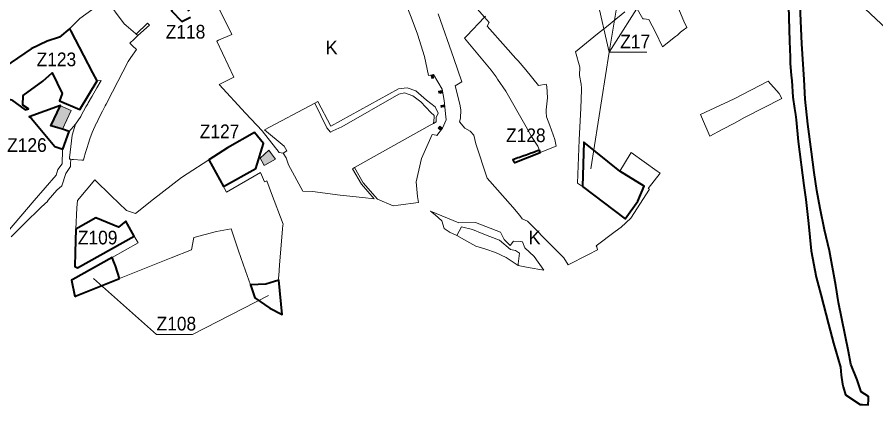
# Model space of a CAD drawing. Extents: x -650276 to -642489, y -1074425 to -1066658.
# Drawn here: x -646722 to -645214, y -1073293 to -1072612 of the extents above; entities that cross this region are included whole.
import ezdxf

# ---------------------------------------------------------------- set-up
doc = ezdxf.new("R2010")
doc.units = 0
doc.header["$LTSCALE"] = 9.6
for name, color, linetype, lineweight in [('1', 7, 'Continuous', 13), ('43', 7, 'Continuous', 13), ('44', 7, 'Continuous', 40), ('45', 7, 'Continuous', 40), ('46', 7, 'Continuous', 13), ('47', 7, 'Continuous', 13)]:
    doc.layers.add(name, color=color, linetype=linetype, lineweight=lineweight)

msp = doc.modelspace()

# ---------------------------------------------------------------- hatches: boundary and pattern name
at = {"layer": '1'}
for points in [[(-645995.13, -1072714.74), (-645994.08, -1072719.72), (-645990.99, -1072719.21), (-645991.83, -1072714.17)], [(-645982.09, -1072742.2), (-645981.54, -1072745.4), (-645979.54, -1072744.94), (-645979.29, -1072745.98), (-645975.96, -1072745.2), (-645976.91, -1072741.11)], [(-646663.07, -1072803.04), (-646653.02, -1072806.07), (-646643.01, -1072809.08), (-646627.38, -1072776.23), (-646636.84, -1072771.74), (-646636.98, -1072772.03), (-646646.39, -1072767.9)], [(-645978.31, -1072767.48), (-645977.69, -1072770.55), (-645976.22, -1072770.26), (-645972.21, -1072769.44), (-645972.83, -1072766.36), (-645976.84, -1072767.17)], [(-645980.16, -1072803.63), (-645976.62, -1072806.59), (-645978.86, -1072809.21), (-645979.48, -1072809.98), (-645982.99, -1072807.15), (-645982.37, -1072806.37)], [(-646295.37, -1072859.86), (-646289.57, -1072870.47), (-646288.95, -1072871.78), (-646287.48, -1072872.3), (-646268.48, -1072861.81), (-646277.43, -1072849.63), (-646280.32, -1072845.93)]]:
    msp.add_hatch(color=256, dxfattribs=at).paths.add_polyline_path(points)

# ---------------------------------------------------------------- linework, layer by layer
for points in [[(-645201.69, -1072577.19), (-645220.27, -1072560.51), (-645223.86, -1072557.28), (-645231.56, -1072550.37), (-645240, -1072542.79), (-645247.59, -1072535.97), (-645252.12, -1072535.29), (-645265.009, -1072538.358), (-645252.768, -1072552.178), (-645248.967, -1072559.511), (-645249.9, -1072561.25), (-645248.8, -1072562.32), (-645250.27, -1072563.1), (-645261.57, -1072569.842), (-645242, -1072588.6), (-645185.95, -1072641.32)], [(-645899.69, -1072610.7), (-645901.33, -1072612.4), (-645935.38, -1072573)], [(-646524.818, -1072657.852), (-646517.19, -1072650.7), (-646511.84, -1072645.84), (-646510.28, -1072644.42), (-646531.13, -1072626.73), (-646534.36, -1072624), (-646566.49, -1072579.96), (-646591.49, -1072599.19), (-646612.66, -1072614.57), (-646618.94, -1072620.88), (-646629.86, -1072632.07), (-646627.32, -1072636.95), (-646605.23, -1072679.37), (-646589.37, -1072709.83)], [(-645635.96, -1072593.24), (-645623.21, -1072614.93), (-645620.91, -1072615.18), (-645612.67, -1072616.12), (-645601.4, -1072638.87), (-645588.81, -1072664.3), (-645565.89, -1072646.15), (-645562.23, -1072643.9), (-645557.19, -1072638.59), (-645554.79, -1072636.89), (-645552.52, -1072635.29), (-645546.18, -1072630.68), (-645551.5, -1072619.44), (-645566.54, -1072582.88)], [(-645982.84, -1072606.46), (-645955.51, -1072684.762), (-645941.146, -1072725.78), (-645953.06, -1072733.07), (-645944.81, -1072765.04), (-645943.38, -1072774.7), (-645943.65, -1072789.47), (-645945.37, -1072795.9), (-645936.23, -1072806.92), (-645926.95, -1072812.63), (-645920.56, -1072819.2), (-645916.48, -1072834.69), (-645896.61, -1072895.14), (-645851.64, -1072945.67), (-645839.57, -1072960.36), (-645835.46, -1072966.49), (-645825.96, -1072970.48), (-645781.57, -1073015.6), (-645767.281, -1073029.7), (-645761.93, -1073034.98), (-645754.82, -1073046.89), (-645741.57, -1073040.34), (-645732.99, -1073036.05), (-645723.5, -1073031.08), (-645719.13, -1073028.84), (-645703.2, -1073020.63), (-645704.37, -1073015.6), (-645705.58, -1073013.4), (-645671.84, -1072988.43), (-645661.51, -1072981.17), (-645644.66, -1072964.8)], [(-645654.16, -1072966.3), (-645729.36, -1072909.65), (-645738.444, -1072903.485), (-645735.02, -1072827.73), (-645732.514, -1072771.845), (-645731.07, -1072739.66), (-645731.28, -1072737.01), (-645731.97, -1072730.04), (-645734.45, -1072714.58), (-645734.19, -1072700.16), (-645741.87, -1072673.02), (-645703.02, -1072641.66), (-645684.57, -1072626.76), (-645677.56, -1072621.1), (-645655.18, -1072603.04)], [(-645936.92, -1072649.21), (-645932.72, -1072644.86), (-645901.33, -1072612.4), (-645893.16, -1072621.85)], [(-645893.16, -1072621.85), (-645897.1, -1072627.93), (-645864.52, -1072664.38), (-645846.45, -1072684.59)], [(-645846.45, -1072684.59), (-645842.51, -1072689.16), (-645828.86, -1072704.98), (-645806.42, -1072732.23), (-645793.25, -1072730.08), (-645792.17, -1072734.14), (-645790.73, -1072753.95), (-645792.92, -1072775.02), (-645793.04, -1072779.12), (-645792.36, -1072786.94), (-645786.89, -1072802.48), (-645778.21, -1072827.14), (-645775.56, -1072838.69), (-645803.84, -1072849.72), (-645805.66, -1072844.58), (-645807.79, -1072838.57), (-645818.73, -1072821.79), (-645828.3, -1072804.78), (-645863.93, -1072742.28), (-645878.65, -1072720.99), (-645881.28, -1072717.18), (-645889.59, -1072705.17), (-645936.92, -1072649.21)], [(-646513.05, -1072668.97), (-646519.93, -1072662.47), (-646524.818, -1072657.852)], [(-646589.37, -1072709.83), (-646581.92, -1072723.91), (-646575.17, -1072723.31), (-646582.42, -1072736.04), (-646590.83, -1072750.81), (-646591.82, -1072752.54), (-646597.52, -1072762.54), (-646598.51, -1072764.27), (-646601.72, -1072769.92), (-646605.93, -1072777.31), (-646610.53, -1072786.11), (-646610.86, -1072786.74), (-646620.27, -1072799.95), (-646625.91, -1072819.66), (-646630.45, -1072858.93), (-646630.57, -1072859.99), (-646630.76, -1072861.61), (-646628.36, -1072861.71), (-646625.96, -1072861.88), (-646625.3, -1072861.92), (-646623.67, -1072862.03), (-646623.25, -1072862.05), (-646608.7, -1072863.05), (-646606.09, -1072863.23), (-646605.32, -1072860.63), (-646602.37, -1072849.93), (-646600.35, -1072843.05), (-646597.38, -1072833.61), (-646594.89, -1072825.68), (-646590.47, -1072814.45), (-646582.98, -1072797.91), (-646582.77, -1072797.45), (-646579.08, -1072789.5), (-646572.45, -1072777.28), (-646567.66, -1072768.09), (-646566, -1072764.9), (-646558.8, -1072750.3), (-646557.83, -1072748.33), (-646555.29, -1072743.47), (-646527.32, -1072689.94), (-646522.77, -1072683), (-646513.05, -1072668.97)], [(-646354.771, -1072919.554), (-646385.86, -1072862.59), (-646423.91, -1072887.04), (-646433.87, -1072893.44), (-646483, -1072931.63), (-646514.85, -1072956.93)], [(-645644.66, -1072964.8), (-645611.65, -1072913.96), (-645613.92, -1072912.93), (-645592.88, -1072886.26), (-645594.56, -1072885.17), (-645598.47, -1072882.66), (-645643.99, -1072849.85), (-645645.63, -1072852.72), (-645663.52, -1072882.58), (-645620.92, -1072908.65), (-645632.23, -1072935.28), (-645654.16, -1072966.3)], [(-646514.85, -1072956.93), (-646530.4, -1072951.72), (-646557.34, -1072925.73), (-646586.22, -1072897.88), (-646616.49, -1072934), (-646617.93, -1072946.87), (-646619.48, -1072984.34), (-646584.23, -1072964.22), (-646544.68, -1072980.62), (-646531.46, -1072970.12), (-646516.7, -1072996.65), (-646514.97, -1072999.69), (-646510.117, -1073008.522), (-646555.79, -1073033.92), (-646550.01, -1073048.55), (-646542.62, -1073071.1), (-646452.08, -1073034.96), (-646415.94, -1073020.53), (-646412.31, -1072999.06), (-646372.47, -1072988.24), (-646346.69, -1072983.91), (-646333.54, -1073022.2), (-646321.46, -1073057.38), (-646312.87, -1073082.4), (-646285.77, -1073081.01), (-646262.94, -1073074.15), (-646263.36, -1073069.88), (-646263.01, -1073065.63), (-646261.54, -1073047.75), (-646256.25, -1072983.65), (-646255.79, -1072978.09), (-646255.41, -1072975.67), (-646275.58, -1072921.83), (-646283.96, -1072899.46), (-646288.06, -1072901.13), (-646294.78, -1072885.04), (-646354.771, -1072919.554)]]:
    msp.add_lwpolyline(points, dxfattribs=at)
for points in [[(-645995.13, -1072714.74), (-645994.08, -1072719.72), (-645990.99, -1072719.21), (-645991.83, -1072714.17)], [(-645505.43, -1072820.89), (-645483.94, -1072809.44), (-645462.66, -1072798.09), (-645444.62, -1072788.65), (-645379.03, -1072755.22), (-645384.11, -1072746.12), (-645403, -1072724.61), (-645463.12, -1072755.6), (-645522.24, -1072783.2)], [(-645982.09, -1072742.2), (-645981.54, -1072745.4), (-645979.54, -1072744.94), (-645979.29, -1072745.98), (-645975.96, -1072745.2), (-645976.91, -1072741.11)], [(-646199.72, -1072763.1), (-646178.75, -1072806.5), (-646171.77, -1072814.14), (-646168.17, -1072812.07), (-646152.26, -1072804.66), (-646052.23, -1072747.56), (-646041.81, -1072745.33), (-646027.3, -1072750.14), (-646013.15, -1072760.96), (-645995.95, -1072779.42), (-645989.88, -1072784.99), (-645990.23, -1072788.27), (-645991.37, -1072798.84), (-645996.8, -1072801.88), (-646129.91, -1072876.24), (-646133.31, -1072878.61), (-646117.66, -1072905.49), (-646095.6, -1072931.21), (-646115.72, -1072928.91), (-646154.82, -1072924.44), (-646203.72, -1072918.45), (-646220.64, -1072917.46), (-646245.69, -1072871.45), (-646250.05, -1072859.17), (-646255.39, -1072850.83), (-646249.04, -1072847.16), (-646253.56, -1072838.8), (-646288.27, -1072810.22)], [(-646663.07, -1072803.04), (-646653.02, -1072806.07), (-646643.01, -1072809.08), (-646627.38, -1072776.23), (-646636.84, -1072771.74), (-646636.98, -1072772.03), (-646646.39, -1072767.9)], [(-645978.31, -1072767.48), (-645977.69, -1072770.55), (-645976.22, -1072770.26), (-645972.21, -1072769.44), (-645972.83, -1072766.36), (-645976.84, -1072767.17)], [(-645980.16, -1072803.63), (-645976.62, -1072806.59), (-645978.86, -1072809.21), (-645979.48, -1072809.98), (-645982.99, -1072807.15), (-645982.37, -1072806.37)], [(-646295.37, -1072859.86), (-646289.57, -1072870.47), (-646288.95, -1072871.78), (-646287.48, -1072872.3), (-646268.48, -1072861.81), (-646277.43, -1072849.63), (-646280.32, -1072845.93)], [(-645949.85, -1072995.57), (-645932.44, -1073005.5), (-645916.47, -1073014.03), (-645899.35, -1073019.65), (-645882.07, -1073025.22), (-645863.39, -1073034.25), (-645842.53, -1073048.19), (-645842.16, -1073045.21), (-645839.85, -1073026.66), (-645847.19, -1073022.14), (-645855.78, -1073020.17), (-645875.33, -1073003.99), (-645892.03, -1072997.34), (-645905.7, -1072991.86), (-645922.38, -1072985.16), (-645941.84, -1072980.05)]]:
    msp.add_lwpolyline(points, close=True, dxfattribs=at)
at = {"layer": '44'}
for points in [[(-645369.364, -1072485.931), (-645372.72, -1072490.314), (-645370.928, -1072496.619), (-645370.755, -1072525.734), (-645368.173, -1072571.881), (-645366.022, -1072654.462), (-645364.524, -1072682.575), (-645364.786, -1072692.977), (-645362.708, -1072714.781)], [(-645338.023, -1072755.969), (-645339.96, -1072721.587), (-645344.152, -1072658.857), (-645347.795, -1072577.893), (-645347.214, -1072540.97), (-645348.253, -1072505.583), (-645347.292, -1072502.877)], [(-645362.708, -1072714.781), (-645361.874, -1072723.527), (-645359.76, -1072752.865), (-645357.272, -1072772.771), (-645355.121, -1072782.993)], [(-645317.65, -1072916.642), (-645322.284, -1072885.085), (-645327.091, -1072848.387), (-645333.718, -1072799.987), (-645338.023, -1072755.969)], [(-645355.121, -1072782.993), (-645354.019, -1072792.454), (-645350.822, -1072830.388), (-645340.345, -1072908.029), (-645337.34, -1072932.073), (-645332.517, -1072974.538), (-645327.554, -1073022.214), (-645319.052, -1073068.6), (-645310.558, -1073098.946), (-645297.395, -1073151.294), (-645288.647, -1073184.518), (-645276.125, -1073226.571), (-645275.269, -1073240.71), (-645272.747, -1073256.762), (-645271.518, -1073261.16)], [(-645304.24, -1072985.372), (-645311.772, -1072947.945), (-645317.65, -1072916.642)], [(-645257.842, -1073221.36), (-645262.388, -1073199.409), (-645279.878, -1073113.356), (-645284.269, -1073083.286), (-645295.788, -1073022.556), (-645304.24, -1072985.372)], [(-645237.524, -1073292.361), (-645227.744, -1073292.735), (-645227.199, -1073283.366), (-645226.847, -1073278.345), (-645239.9, -1073270.025), (-645247.051, -1073248.736), (-645257.842, -1073221.36)], [(-645271.518, -1073261.16), (-645267.525, -1073275.443), (-645241.72, -1073292.2), (-645237.524, -1073292.361)]]:
    msp.add_lwpolyline(points, dxfattribs=at)
at = {"layer": '45'}
for points in [[(-646420.36, -1072601.78), (-646427.95, -1072588.07), (-646432.57, -1072579.75), (-646433.36, -1072578.45), (-646451.458, -1072601.008), (-646433.024, -1072620.04), (-646417.787, -1072612.168)], [(-646737.05, -1072756.4), (-646732.5, -1072757.63), (-646708.65, -1072775.02), (-646702.45, -1072773.39), (-646712.46, -1072766.76), (-646711.79, -1072750.02), (-646677.39, -1072724.85), (-646660.89, -1072709.97), (-646643.36, -1072746.04), (-646647.93, -1072759.01), (-646612.11, -1072774.56), (-646581.92, -1072723.91), (-646589.37, -1072709.83), (-646605.23, -1072679.37), (-646627.32, -1072636.95), (-646629.86, -1072632.07), (-646648.27, -1072647.48), (-646669.6, -1072654.53), (-646697.89, -1072667.65)], [(-646697.89, -1072667.65), (-646732.95, -1072691.68), (-646759.491, -1072709.878), (-646757.5, -1072713.3), (-646747.87, -1072729.85), (-646744.94, -1072734.88), (-646748.3, -1072737.01), (-646737.05, -1072756.4)], [(-646653.02, -1072806.07), (-646663.07, -1072803.04), (-646663.07, -1072803.04), (-646646.12, -1072767.32), (-646646.31, -1072767.388), (-646701.12, -1072787.08), (-646697.09, -1072790.03), (-646656.36, -1072839.08)], [(-646656.36, -1072839.08), (-646642.404, -1072844.195), (-646631.08, -1072812.68), (-646643.01, -1072809.08), (-646651.11, -1072806.64), (-646653.02, -1072806.07)], [(-645849.703, -1072867.622), (-645848.52, -1072867.16), (-645803.84, -1072849.72), (-645805.159, -1072845.994)], [(-645805.159, -1072845.994), (-645808.177, -1072847.063), (-645811.148, -1072848.124), (-645813.978, -1072849.124), (-645816.948, -1072850.184), (-645819.779, -1072851.184), (-645822.726, -1072852.233), (-645825.527, -1072853.233), (-645828.409, -1072854.254), (-645834.208, -1072856.314)], [(-645834.208, -1072856.314), (-645837.027, -1072857.313), (-645839.908, -1072858.343), (-645842.74, -1072859.344), (-645845.619, -1072860.364), (-645848.628, -1072861.433), (-645851.48, -1072862.586), (-645850.187, -1072866.251), (-645850.17, -1072866.3), (-645849.705, -1072867.618), (-645849.703, -1072867.622)], [(-646542.62, -1073071.1), (-646550.01, -1073048.55), (-646552.79, -1073041.53), (-646555.79, -1073033.92), (-646624.69, -1073072.66), (-646626.967, -1073073.918), (-646621.38, -1073102.66)], [(-646542.62, -1073071.1), (-646550.01, -1073048.55), (-646552.79, -1073041.53), (-646555.79, -1073033.92), (-646624.69, -1073072.66), (-646626.967, -1073073.918), (-646621.38, -1073102.66)], [(-646542.62, -1073071.1), (-646550.01, -1073048.55), (-646552.79, -1073041.53), (-646555.79, -1073033.92), (-646624.69, -1073072.66), (-646626.967, -1073073.918), (-646621.38, -1073102.66)], [(-646542.62, -1073071.1), (-646550.01, -1073048.55), (-646552.79, -1073041.53), (-646555.79, -1073033.92), (-646624.69, -1073072.66), (-646626.967, -1073073.918), (-646621.38, -1073102.66)], [(-646621.38, -1073102.66), (-646620.19, -1073102.14), (-646618.56, -1073101.42), (-646542.62, -1073071.1)], [(-646621.38, -1073102.66), (-646620.19, -1073102.14), (-646618.56, -1073101.42), (-646542.62, -1073071.1)], [(-646621.38, -1073102.66), (-646620.19, -1073102.14), (-646618.56, -1073101.42), (-646542.62, -1073071.1)], [(-646621.38, -1073102.66), (-646620.19, -1073102.14), (-646618.56, -1073101.42), (-646542.62, -1073071.1)], [(-646262.94, -1073074.15), (-646285.77, -1073081.01), (-646312.87, -1073082.4), (-646305.18, -1073104.8), (-646278.38, -1073123.25)], [(-646262.94, -1073074.15), (-646285.77, -1073081.01), (-646312.87, -1073082.4), (-646305.18, -1073104.8), (-646278.38, -1073123.25)], [(-646278.38, -1073123.25), (-646257.09, -1073134.01), (-646262.94, -1073074.15)], [(-646278.38, -1073123.25), (-646257.09, -1073134.01), (-646262.94, -1073074.15)]]:
    msp.add_lwpolyline(points, dxfattribs=at)
for points in [[(-646360.22, -1072909.57), (-646303.02, -1072877.74), (-646289.63, -1072834.04), (-646305.56, -1072814.43), (-646353.25, -1072841.63), (-646385.86, -1072862.59)], [(-645729.36, -1072909.65), (-645654.16, -1072966.3), (-645632.23, -1072935.28), (-645620.92, -1072908.65), (-645663.52, -1072882.58), (-645726.9, -1072831.5)], [(-645729.36, -1072909.65), (-645654.16, -1072966.3), (-645632.23, -1072935.28), (-645620.92, -1072908.65), (-645663.52, -1072882.58), (-645726.9, -1072831.5)], [(-646516.7, -1072996.65), (-646531.46, -1072970.12), (-646544.68, -1072980.62), (-646584.23, -1072964.22), (-646619.48, -1072984.34), (-646620.71, -1073025.49), (-646621.44, -1073049.79), (-646616.55, -1073052.21)], [(-646516.7, -1072996.65), (-646531.46, -1072970.12), (-646544.68, -1072980.62), (-646584.23, -1072964.22), (-646619.48, -1072984.34), (-646620.71, -1073025.49), (-646621.44, -1073049.79), (-646616.55, -1073052.21)]]:
    msp.add_lwpolyline(points, close=True, dxfattribs=at)
at = {"layer": '46'}
for p, q in [((-645682.434, -1072673.943), (-645625.498, -1072333.934)), ((-645682.434, -1072673.943), (-645539.175, -1072448)), ((-645682.434, -1072673.943), (-645729.938, -1072467.657)), ((-645682.434, -1072673.943), (-645714.669, -1072878.528)), ((-645682.434, -1072673.943), (-645714.669, -1072878.528)), ((-645616.267, -1072673.943), (-645682.434, -1072673.943))]:
    msp.add_line(p, q, dxfattribs=at)
msp.add_lwpolyline([(-646588.523, -1073070.963), (-646477.555, -1073169.273), (-646414.561, -1073169.273), (-646281.126, -1073101.085)], dxfattribs=at)
msp.add_lwpolyline([(-646588.523, -1073070.963), (-646477.555, -1073169.273), (-646414.561, -1073169.273), (-646281.126, -1073101.085)], dxfattribs=at)
at = {"layer": '47'}
msp.add_line((-645882.07, -1073025.22), (-645863.39, -1073034.25), dxfattribs=at)
for points in [[(-645999.622, -1072714.927), (-646006.66, -1072681.4), (-646019.16, -1072642.35), (-646030.17, -1072612.31), (-646043.87, -1072578.12), (-646056.42, -1072556.49), (-646075.82, -1072525.54), (-646110.61, -1072477.49), (-646153.49, -1072431.54), (-646172.81, -1072418.2), (-646184.449, -1072410.256), (-646194.19, -1072404.62), (-646254.75, -1072404.25), (-646243.17, -1072432.88), (-646282.47, -1072474.34), (-646328.45, -1072504.81), (-646315.452, -1072531.573)], [(-646315.452, -1072531.573), (-646320.62, -1072534.6), (-646350.18, -1072550.59), (-646382.41, -1072568.01), (-646345.6, -1072642.55), (-646368.51, -1072652.81), (-646371.66, -1072654.2), (-646342.08, -1072717.43), (-646367.72, -1072730.68), (-646321.171, -1072780.535), (-646292.17, -1072811.6), (-646261.97, -1072849.66), (-646255.39, -1072850.83), (-646249.04, -1072847.16), (-646253.56, -1072838.8), (-646288.27, -1072810.22), (-646199.72, -1072763.1), (-646194.296, -1072760.193)], [(-645969.46, -1072787.03), (-645972.31, -1072758.48), (-645975.86, -1072738.61), (-645991.31, -1072712.86), (-645996.31, -1072714.11), (-645999.622, -1072714.927)], [(-646194.296, -1072760.193), (-646171.72, -1072803.51), (-646052.58, -1072737.82), (-646037.23, -1072736.38), (-646022.4, -1072741.58), (-646003.22, -1072757.85), (-645988.43, -1072769.93), (-645983.22, -1072780.88), (-645986.24, -1072788.33), (-645986.359, -1072796.127)], [(-645975.3, -1072807.37), (-645969.01, -1072792.28), (-645969.46, -1072787.03)], [(-646732.95, -1072998.07), (-646710.3, -1072975.31), (-646680.07, -1072945.74), (-646668.53, -1072935.52), (-646669.198, -1072934.569), (-646668.09, -1072933.43), (-646652.76, -1072915.66), (-646644.069, -1072908.218), (-646644.061, -1072908.209), (-646644.059, -1072908.208), (-646637.2, -1072886.57), (-646628.7, -1072874.5), (-646628.58, -1072869.88), (-646628.36, -1072861.71), (-646630.76, -1072861.61), (-646630.57, -1072859.99), (-646630.45, -1072858.93), (-646625.91, -1072819.66), (-646620.27, -1072799.95), (-646631.08, -1072812.68), (-646640.313, -1072838.394), (-646642.404, -1072844.195), (-646642.39, -1072844.2), (-646642.438, -1072844.29), (-646642.939, -1072845.68), (-646643.574, -1072869.57), (-646650.798, -1072879.828), (-646653.846, -1072889.44), (-646692.432, -1072934.135), (-646739.241, -1072988.798)], [(-645986.359, -1072796.127), (-645991.37, -1072798.84), (-645996.8, -1072801.88), (-646129.91, -1072876.24), (-646114.5, -1072902.8), (-646089.39, -1072931.92), (-646062.04, -1072943.58), (-646053.287, -1072942.399), (-646017.65, -1072937.59), (-646019.21, -1072926.91), (-646021.64, -1072901.6), (-646012.37, -1072860.3), (-645993.47, -1072818.44), (-645986.71, -1072819.26), (-645985.19, -1072819.72), (-645975.3, -1072807.37)], [(-645866.93, -1073002.72), (-645873.3, -1072989.79), (-645917.53, -1072972.93), (-645946.4, -1072973.05), (-645996.2, -1072952.69)], [(-645996.2, -1072952.69), (-645988.49, -1072959.28), (-645976.48, -1072969.55), (-645972.6, -1072983.41)], [(-645972.6, -1072983.41), (-645963.77, -1072989), (-645962.81, -1072989.45), (-645949.85, -1072995.57), (-645932.44, -1073005.5), (-645916.47, -1073014.03), (-645899.35, -1073019.65), (-645882.07, -1073025.22)], [(-645838.89, -1073006.18), (-645850.37, -1073005.42), (-645856.46, -1073013.07), (-645858.82, -1073010.74), (-645866.93, -1073002.72)], [(-645830.6, -1073016.92), (-645834.9, -1073006.45), (-645838.89, -1073006.18)], [(-645863.39, -1073034.25), (-645842.53, -1073048.19), (-645824.93, -1073051.83), (-645797.32, -1073056.62), (-645814.27, -1073032.11), (-645830.6, -1073016.92)]]:
    msp.add_lwpolyline(points, dxfattribs=at)
msp.add_lwpolyline([(-646493.229, -1072622.74), (-646513.209, -1072641.935), (-646510.28, -1072644.42), (-646490.11, -1072626.15)], close=True, dxfattribs=at)

# ---------------------------------------------------------------- texts
at = {"layer": '43'}
for p in [(-646180.786, -1072677.559), (-646180.786, -1072677.559), (-645824.362, -1073011.011), (-645824.362, -1073011.011)]:
    msp.add_text('K', height=24, dxfattribs=at).set_placement(p)
at = {"layer": '46', "width": 0.95}
for s, p in [('Z118', (-646461.466, -1072649.857)), ('Z17', (-645663.172, -1072666.966)), ('Z123', (-646688.261, -1072698.34)), ('Z127', (-646401.702, -1072824.699)), ('Z128', (-645863.685, -1072831.559)), ('Z126', (-646740.041, -1072848.718)), ('Z109', (-646615.842, -1073011.142)), ('Z109', (-646615.842, -1073011.142)), ('Z108', (-646477.565, -1073162.229)), ('Z108', (-646477.565, -1073162.229))]:
    msp.add_text(s, height=24, dxfattribs=at).set_placement(p)

doc.saveas('drawing.dxf')
